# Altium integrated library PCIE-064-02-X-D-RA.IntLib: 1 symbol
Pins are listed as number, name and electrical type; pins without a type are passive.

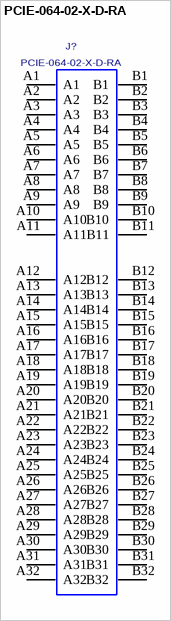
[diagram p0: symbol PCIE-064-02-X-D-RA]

## PCIE-064-02-X-D-RA
designator J?
PCI EXPRESS RIGHT ANGLE ASSEMBLY,64PINS.; MANUFACTURER: SAMTEC
footprint PCIE-064-02-X-D-RA
pins: A1, A2, A3, A4, A5, A6, A7, A8, A9, A10, A11, A12, A13, A14, A15, A16, A17, A18, A19, A20, A21, A22, A23, A24, A25, A26, A27, A28, A29, A30, A31, A32, B1, B2, B3, B4, B5, B6, B7, B8, B9, B10, B11, B12, B13, B14, B15, B16, B17, B18, B19, B20, B21, B22, B23, B24, B25, B26, B27, B28, B29, B30, B31, B32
